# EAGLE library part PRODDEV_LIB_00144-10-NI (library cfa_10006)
2X5 HDR, CONN HDR BRKWAY .100 VERT
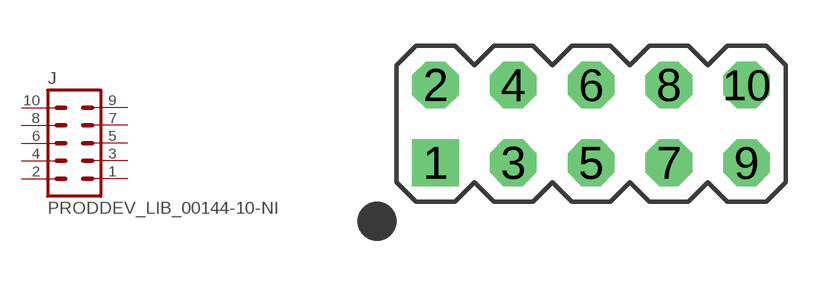
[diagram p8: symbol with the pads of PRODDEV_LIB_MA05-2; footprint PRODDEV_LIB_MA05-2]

Designator prefix J

## PRODDEV_LIB_00144-10-NI  [PRODDEV_LIB_MA05-2]
1  1  pas
2  2  pas
3  3  pas
4  4  pas
5  5  pas
6  6  pas
7  7  pas
8  8  pas
9  9  pas
10  10  pas

## Footprint PRODDEV_LIB_MA05-2 (pad centres in mm)
PIN HEADER
drill 1.016 square: 1 -5.08,-1.27
drill 1.016 octagon: 2 -5.08,1.27; 3 -2.54,-1.27; 4 -2.54,1.27; 5 0,-1.27; 6 0,1.27; 7 2.54,-1.27; 8 2.54,1.27; 9 5.08,-1.27; 10 5.08,1.27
